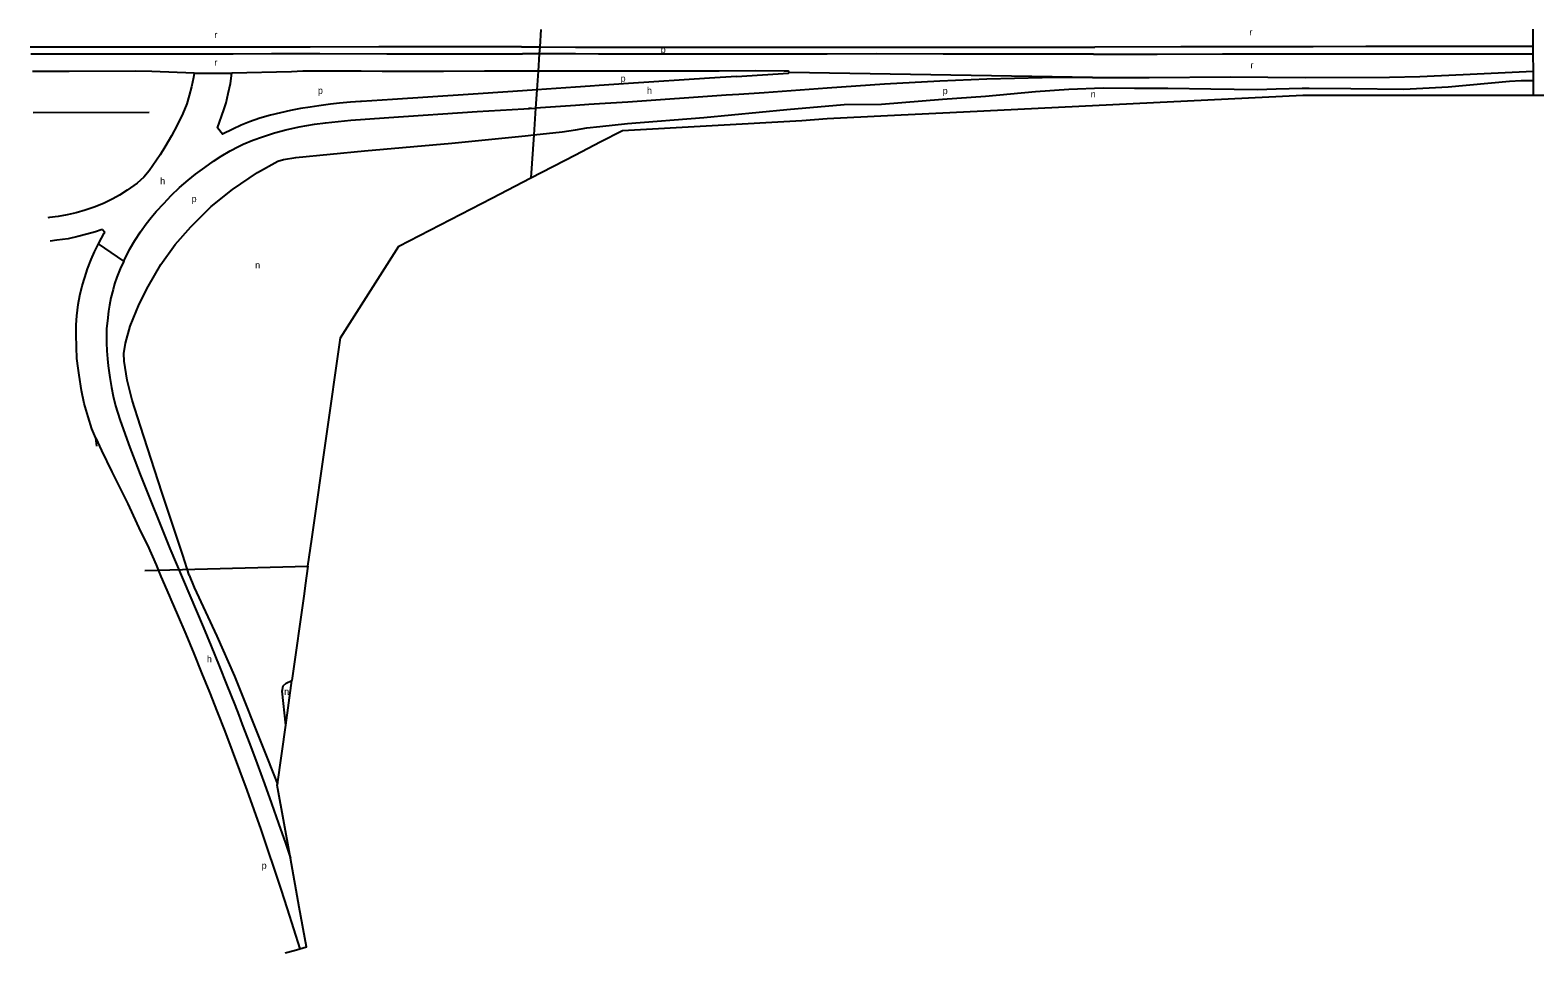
# Model space of a CAD drawing. Extents: x 162667 to 164645, y 379003 to 382150.
# Drawn here: x 163025 to 163924, y 379003 to 379554 of the extents above; entities that cross this region are included whole.
import ezdxf

# ---------------------------------------------------------------- set-up
doc = ezdxf.new("R2010")
doc.units = 0
for name, color, linetype in [('BLT_Basislijn', 7, 'Continuous'), ('BLT_Centroide', 7, 'Continuous'), ('BLT_Gemeentegrens', 7, 'Continuous'), ('BLT_Hoogspanningsmast_en_leidingen', 7, 'Continuous'), ('BLT_Vlakafsluiter', 7, 'Continuous')]:
    doc.layers.add(name, color=color, linetype=linetype)

msp = doc.modelspace()

# ---------------------------------------------------------------- linework, layer by layer
at = {"layer": 'BLT_Basislijn'}
for p, q in [((163920.8, 379554.49), (163920.88, 379544.06)), ((163145.77, 379543.74), (163103.83, 379543.68)), ((163103.83, 379539.79), (163145.89, 379539.77)), ((163317.76, 379543.84), (163328.64, 379543.79)), ((163328.36, 379539.64), (163318.35, 379539.65)), ((163350, 379539.61), (163328.36, 379539.64)), ((163328.64, 379543.79), (163350, 379543.7)), ((163920.88, 379544.06), (163920.89, 379542.16)), ((163920.89, 379542.16), (163920.93, 379539.75)), ((163920.93, 379539.75), (163921.08, 379529.44)), ((163122.44, 379528.23), (163144.9, 379528.21)), ((163921.08, 379529.44), (163921.09, 379528.57)), ((163921.09, 379528.57), (163921.11, 379523.7)), ((163921.11, 379523.7), (163921.15, 379515.11)), ((163285.94, 379515.48), (163240.72, 379512.42)), ((163026.57, 379504.63), (163095.69, 379504.84)), ((163323.75, 379507.11), (163321.82, 379506.98)), ((163350, 379508.92), (163326.13, 379507.23)), ((163067.79, 379434.95), (163069.34, 379433.37))]:
    msp.add_line(p, q, dxfattribs=at)
for points in [[(163103.83, 379543.68), (163072.4, 379543.65), (163024.73, 379543.65)], [(163025.13, 379539.76), (163029.36, 379539.76), (163073.42, 379539.78), (163103.83, 379539.79)], [(163317.76, 379543.84), (163269.16, 379543.86), (163232.71, 379543.93), (163191.73, 379543.72), (163168.45, 379543.74), (163145.77, 379543.74)], [(163145.89, 379539.77), (163168.59, 379539.81), (163197.57, 379539.85), (163237.53, 379539.65), (163283.11, 379539.65), (163318.35, 379539.65)], [(163350, 379543.7), (163363.66, 379543.64)], [(163363.73, 379539.59), (163350, 379539.61)], [(163363.66, 379543.64), (163370.29, 379543.61), (163416.98, 379543.64), (163459.74, 379543.67), (163499.83, 379543.69), (163535.39, 379543.65), (163571.07, 379543.66), (163605.11, 379543.68), (163628.38, 379543.66), (163659.73, 379543.75)], [(163658.81, 379539.57), (163615.41, 379539.58), (163569.26, 379539.58), (163529.69, 379539.61), (163500, 379539.57), (163470.7, 379539.54), (163439.93, 379539.56), (163400.13, 379539.58), (163363.73, 379539.59)], [(163658.81, 379539.57), (163696.88, 379539.59), (163735.81, 379539.65), (163775.25, 379539.63), (163821.74, 379539.61), (163864.27, 379539.67), (163920.93, 379539.75)], [(163920.88, 379544.06), (163886.11, 379544.03), (163847.65, 379544.02), (163821.28, 379544.03), (163789.87, 379543.9), (163749.79, 379543.89), (163710.9, 379543.82), (163659.73, 379543.75)], [(163122.44, 379528.23), (163097.31, 379529.07), (163087.26, 379529.28), (163047.94, 379529.24), (163026.22, 379529.23)], [(163122.44, 379528.23), (163122.09, 379525.54), (163120.99, 379520.07), (163119.59, 379514.76), (163118.07, 379509.87), (163115.68, 379504.03), (163112.45, 379497.15), (163108.98, 379490.71), (163105.02, 379483.93), (163102.23, 379479.44), (163095.61, 379469.94), (163092.47, 379466.08), (163088.49, 379462.56), (163082.66, 379458.26), (163078.03, 379455.34), (163073.97, 379453.22), (163068.86, 379450.59), (163063.56, 379448.41), (163057.52, 379446.32), (163052.23, 379444.83), (163046.8, 379443.57), (163041.42, 379442.61), (163036.2, 379441.94), (163035.27, 379441.87)], [(163240.72, 379512.42), (163222.3, 379511.19), (163221.68, 379511.2), (163215.79, 379510.77), (163209.13, 379510.2), (163203.93, 379509.61), (163196.9, 379508.73), (163191.62, 379507.94), (163185.93, 379507.05), (163179.95, 379505.85), (163173.97, 379504.53), (163167.98, 379503.08), (163161.77, 379501.24), (163155.49, 379499.07), (163150.61, 379497.14), (163145.65, 379494.77), (163139.46, 379491.7), (163136.43, 379495.64), (163140.26, 379506.31), (163141.69, 379510.41), (163142.89, 379516.09), (163144.15, 379521.97), (163144.9, 379528.21)], [(163320.81, 379529.27), (163295.62, 379529.38), (163271.3, 379529.21), (163246.4, 379529.23), (163234.61, 379529.14), (163222.19, 379529.29), (163207.67, 379529.35), (163187.33, 379529.28), (163180.58, 379528.96), (163144.9, 379528.21)], [(163327.64, 379529.28), (163320.81, 379529.27)], [(163350, 379529.3), (163342.75, 379529.29), (163327.64, 379529.28)], [(163363.92, 379529.3), (163350, 379529.3)], [(163477.41, 379528.62), (163477.18, 379529.07), (163476.74, 379529.3), (163474.36, 379529.33), (163457.58, 379529.48), (163435.67, 379529.37), (163403.93, 379529.29), (163371.83, 379529.31), (163363.92, 379529.3)], [(163445.92, 379526.16), (163476.93, 379528.13), (163477.41, 379528.62)], [(163658.24, 379525.55), (163692, 379525.48), (163740.3, 379525.89), (163785.21, 379525.64), (163835.37, 379525.8), (163853.37, 379526.18), (163879.28, 379527.32), (163921.08, 379529.44)], [(163326.89, 379518.22), (163312.65, 379517.25), (163285.94, 379515.48)], [(163350, 379519.8), (163326.89, 379518.22)], [(163364.07, 379520.75), (163358.66, 379520.4), (163350, 379519.8)], [(163445.92, 379526.16), (163429.81, 379525.11), (163381.6, 379521.91), (163364.07, 379520.75)], [(163658.24, 379525.55), (163628.2, 379525.39), (163595.28, 379524.54), (163567.28, 379523.44), (163534.27, 379521.68), (163500.09, 379519.29), (163462.42, 379516.45), (163447.29, 379515.45)], [(163532.44, 379509.6), (163568.73, 379512.61), (163594.4, 379514.53), (163624.21, 379517.29), (163644.14, 379518.55), (163664.69, 379519.42), (163683.39, 379519.19), (163703.26, 379519.29), (163728.81, 379518.78), (163756.67, 379518.39), (163767.79, 379518.72), (163783.26, 379519.16), (163787.48, 379519.13), (163812.38, 379518.95), (163844.01, 379518.58), (163870.29, 379520.01), (163907.04, 379523.38)], [(163907.04, 379523.38), (163913.88, 379523.7), (163921.11, 379523.7)], [(163364.27, 379509.86), (163357.83, 379509.46), (163350, 379508.92)], [(163447.29, 379515.45), (163439.87, 379514.95), (163381.21, 379510.92), (163364.27, 379509.86)], [(163364.51, 379496.36), (163380.97, 379498.15), (163426.46, 379501.75), (163475.92, 379506.48), (163510.13, 379509.43), (163532.44, 379509.6)], [(163856.49, 379515.11), (163856.48, 379515.1)], [(163080.59, 379416.07), (163084.05, 379423.02), (163087.1, 379428.25), (163090.55, 379433.52), (163094.01, 379438.18), (163096.88, 379441.99), (163099.92, 379445.7), (163104.35, 379450.4), (163108.76, 379455.1), (163113.8, 379459.84), (163118.88, 379464.25), (163123.35, 379467.86), (163128.83, 379471.97), (163134.13, 379475.65), (163138.63, 379478.59), (163144.1, 379481.8), (163149.06, 379484.43), (163149.77, 379484.78), (163151.66, 379485.71), (163157.46, 379488.13), (163163.19, 379490.2), (163170.38, 379492.59), (163177.18, 379494.38), (163185.25, 379496.11), (163194.22, 379497.65), (163200.9, 379498.53), (163208.46, 379499.37), (163215.94, 379500.02), (163224.54, 379500.71), (163238.59, 379501.68), (163291.3, 379505.19), (163326.13, 379507.23)], [(163119.63, 379228.54), (163115.69, 379240.48), (163103.27, 379278.18), (163090.51, 379317.47), (163085.57, 379333.1), (163082.53, 379344.89), (163080.74, 379356.25), (163080.52, 379360.83), (163081.52, 379367.03), (163084.28, 379377.15), (163089.77, 379390.37), (163095.07, 379400.94), (163102.66, 379414.04), (163111.21, 379425.94), (163120.54, 379436.52), (163132.64, 379448.58), (163145.43, 379458.82), (163160.23, 379468.87), (163172.53, 379475.69), (163175.81, 379476.74), (163183.12, 379477.81), (163224.14, 379481.87), (163276.12, 379486.49), (163319.88, 379490.8), (163325.04, 379491.35)], [(163325.04, 379491.35), (163342.07, 379493.17), (163350, 379494.44)], [(163350, 379494.44), (163356.69, 379495.51), (163364.51, 379496.36)], [(163323.28, 379465.7), (163323.28, 379465.7)], [(163067.79, 379434.95), (163067.02, 379434.62), (163063.67, 379433.56), (163058.5, 379431.99), (163053.12, 379430.62), (163047.42, 379429.4), (163040.71, 379428.45), (163036.71, 379427.98)], [(163065.51, 379426.36), (163067.26, 379429.68), (163068.95, 379432.75), (163069.34, 379433.37)], [(163063.82, 379310.28), (163061.56, 379315.83), (163059.29, 379323.07), (163056.97, 379331.04), (163055.39, 379338.85), (163053.91, 379348.04), (163053.27, 379352.04), (163052.64, 379357.95), (163052.27, 379364.71), (163052.1, 379372.3), (163052.26, 379377.95), (163052.63, 379383.28), (163053.42, 379390.04), (163054.39, 379395.48), (163055.71, 379401.24), (163057.24, 379406.15), (163058.93, 379411.48), (163061.13, 379416.91), (163063.14, 379421.61), (163065.51, 379426.36)], [(163080.59, 379416.07), (163078.39, 379411.37), (163076.5, 379406.33), (163075.09, 379402.38), (163074.24, 379398.97), (163072.91, 379394.02), (163072.13, 379389.67), (163071.47, 379386.07), (163070.8, 379380.37), (163070.32, 379375.75), (163070.18, 379372.05), (163070.33, 379367.28), (163070.48, 379362.45), (163070.84, 379357.75), (163071.21, 379353.42), (163072.16, 379346.5), (163073.16, 379340.59), (163074.27, 379335.41), (163075.64, 379329.66), (163078.28, 379321.42), (163081.35, 379312.54), (163084.15, 379304.78), (163087.1, 379297.12), (163090.43, 379288.59), (163108, 379244.57)], [(163063.82, 379310.28), (163067.26, 379303.01), (163073.45, 379290.35), (163082.89, 379271.07), (163090.6, 379254.7), (163094.71, 379246.42), (163099.81, 379234.77), (163102.23, 379228.71), (163102.63, 379227.83), (163107.63, 379216.41)], [(163064.53, 379305.48), (163063.82, 379310.28)], [(163108, 379244.57), (163127.84, 379197.77), (163132.67, 379186.17), (163137.43, 379174.54), (163142.11, 379162.88), (163146.72, 379151.19), (163149.08, 379145.12), (163151.26, 379139.47), (163155.73, 379127.73), (163160.12, 379115.95), (163164.44, 379104.15), (163168.68, 379092.33), (163172.86, 379080.48), (163176.95, 379068.6), (163179.96, 379059.69)], [(163119.63, 379228.54), (163122.6, 379221.31), (163136, 379192.15), (163146.56, 379168.24), (163164.73, 379122.92), (163170.51, 379108.5), (163172.17, 379103.87)], [(163107.63, 379216.41), (163107.64, 379216.39), (163108.6, 379214.16)], [(163108.6, 379214.16), (163112.59, 379204.91), (163117.47, 379193.41), (163122.27, 379181.87), (163127, 379170.31), (163131.66, 379158.72), (163136.25, 379147.09), (163140.76, 379135.44), (163145.2, 379123.76), (163149.57, 379112.06), (163153.86, 379100.32), (163158.08, 379088.56), (163162.23, 379076.77), (163166.31, 379064.96), (163170.3, 379053.12), (163174.23, 379041.26), (163178.08, 379029.38), (163181.86, 379017.46), (163185.52, 379005.66)], [(163177.12, 379139.17), (163174.96, 379159.43), (163175.6, 379162.53), (163177.35, 379164.18), (163180.84, 379165.73)]]:
    msp.add_lwpolyline(points, dxfattribs=at)
at = {"layer": 'BLT_Gemeentegrens'}
for p, q in [((163856.49, 379515.11), (163921.15, 379515.11)), ((163921.15, 379515.11), (163927.36, 379515.11)), ((163323.28, 379465.7), (163350, 379479.52)), ((163177.12, 379139.17), (163180.84, 379165.73))]:
    msp.add_line(p, q, dxfattribs=at)
for points in [[(163535.93, 379502.88), (163581.27, 379505.05), (163783.73, 379515.11), (163856.49, 379515.11)], [(163485, 379500), (163500, 379501.15), (163535.93, 379502.88)], [(163364.68, 379487.11), (163378.01, 379494.01), (163485, 379500)], [(163350, 379479.52), (163364.68, 379487.11)], [(163190.4, 379233.98), (163192.65, 379250), (163209.71, 379370.25), (163244.56, 379424.98), (163300, 379453.66), (163323.28, 379465.7)], [(163190.4, 379233.98), (163188.8, 379222.52), (163188.1, 379217.52), (163180.84, 379165.73)], [(163172.17, 379103.87), (163177.12, 379139.17)], [(163179.96, 379059.69), (163172.08, 379103.21), (163172.17, 379103.87)], [(163185.52, 379005.66), (163189.54, 379006.79), (163185.24, 379030.53), (163179.96, 379059.69)], [(163176.71, 379003.2), (163182.12, 379004.71), (163185.52, 379005.66)]]:
    msp.add_lwpolyline(points, dxfattribs=at)
at = {"layer": 'BLT_Hoogspanningsmast_en_leidingen'}
msp.add_line((163093.19, 379231.42), (163190.4, 379233.98), dxfattribs=at)
at = {"layer": 'BLT_Vlakafsluiter'}
for p, q in [((163329.36, 379554.26), (163328.64, 379543.79)), ((163328.36, 379539.64), (163327.64, 379529.28)), ((163328.64, 379543.79), (163328.36, 379539.64)), ((163327.64, 379529.28), (163326.89, 379518.22)), ((163658.24, 379525.55), (163477.41, 379528.62)), ((163326.89, 379518.22), (163326.13, 379507.23)), ((163326.13, 379507.23), (163325.04, 379491.35)), ((163325.04, 379491.35), (163323.28, 379465.7)), ((163080.59, 379416.07), (163065.51, 379426.36))]:
    msp.add_line(p, q, dxfattribs=at)

# ---------------------------------------------------------------- texts
at = {"layer": 'BLT_Centroide'}
for s, p in [('r', (163134.56, 379549.11)), ('r', (163751.83, 379550.65)), ('p', (163400.77, 379540.21)), ('r', (163134.56, 379532.59)), ('r', (163752.44, 379531)), ('p', (163196.33, 379515.81)), ('p', (163376.84, 379523.02)), ('h', (163392.54, 379515.83)), ('p', (163568.93, 379515.65)), ('n', (163657.21, 379513.74)), ('h', (163102.26, 379461.84)), ('p', (163121, 379451.2)), ('n', (163158.91, 379411.68)), ('h', (163130.12, 379176.56)), ('n', (163176.21, 379157.13)), ('p', (163162.79, 379053.39))]:
    msp.add_text(s, height=4, dxfattribs=at).set_placement(p)

doc.saveas('drawing.dxf')
